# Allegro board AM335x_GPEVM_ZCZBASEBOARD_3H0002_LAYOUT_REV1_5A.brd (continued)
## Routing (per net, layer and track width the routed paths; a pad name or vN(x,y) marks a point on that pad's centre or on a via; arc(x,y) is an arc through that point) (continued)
GND_ETH: length 22.4
  TOP w0.508: C272.2 J15.SHLD1 J15.SHLD2 C271.2
GND_OSC0: length 14.5
  TOP w0.254: v1(100.29,83.02) 100.29,84.19 98.58,85.89 95.19,85.89 94.23,86.85 93.53,86.85 93.12,86.44 92.31,86.44 92.07,86.2 U2.V11 ; C4.2 102.02,81.19 101.64,81.57 v1(101.64,81.83) 101.64,82.08 C5.2
  BOTTOM w0.254: v1(100.29,83.02) 100.6,82.71 100.62,82.71 C67.2 101,82.33 101.13,82.33 v1(101.64,81.83)
GND_OSC1: length 13.8
  TOP w0.102: U2.A5 77.94,81.14 77.1,81.14
  TOP w0.121: 77.1,81.14 76.22,81.14 75.24,80.16 71.56,80.16 71.31,79.92 67.56,79.92 C2.1 C3.1
GNDA_ADC: length 44.3
  TOP w0.305: v2(81,83.4) U2.E8
  TOP w0.508: v1(49.44,75.73) v1(57.19,75.73) ; v1(58.9,84.75) 59.66,84.75 59.92,84.49 64.16,84.49 v1(64.17,84.5) 64.41,84.75 R45.1
  BOTTOM w0.127: 79.56,82.99 79.79,83.22 79.79,83.6 80.05,83.86 80.54,83.86 v2(81,83.4)
  BOTTOM w0.152: 77.15,83.1 79.03,83.1 79.13,82.99 79.56,82.99
  BOTTOM w0.508: v1(58.9,84.75) 58.89,84.73 58.89,81.93 58.88,81.93 58.88,80.73 57.19,79.03 v1(57.19,75.73) ; C63.2 v1(49.44,75.73) ; 77.15,83.1 76.04,83.1 FB10.1 74.46,82.77 74.46,82.97 74.08,83.35 73.06,83.35 72.16,84.25 71.27,84.25 71.03,84.49 R461.1 64.19,84.49 v1(64.17,84.5)
GNDA_TSC: length 61.2
  TOP w0.121: R45.2 57.12,83.73 53.95,80.56 47.98,80.56 46.69,79.27 44.4,79.27 43.61,80.07 43.61,80.09 v1(43.29,80.4) ; 49.82,57.31 J9.11
  TOP w0.508: R45.2 65.19,83.48 R51.2 C13.2 C14.2 C11.2 C12.2
  BOTTOM w0.121: 49.82,57.31 50.96,57.31 51.22,57.57 51.22,64.68 50.07,65.83 47.73,65.83 42.18,71.38 42.18,79.29 v1(43.29,80.4)
GNDUSB0: length 26
  TOP w0.635: v1(124.62,168.26) 124.91,168.55 J14.S4 126.62,166.82 126.87,166.57 126.87,166 J14.S2 ; J14.S1 134.08,166 134.82,166.74 J14.S3 136.66,168.55 v1(136.94,168.26) FB14.2
  BOTTOM w0.635: v1(124.62,168.26) v1(136.94,168.26)
GNDUSB1: length 16.7
  TOP w0.635: J18.S1 154.6,165.66 FB19.2
  BOTTOM w0.635: J18.S1 151.94,168.31 139.98,168.31 J18.S2
GNDUSBJ: length 24.9
  TOP w0.635: FB25.1 2.02,92.62 v1(1.64,93) 1.64,95.17 J40.S4 3.3,95.38 3.98,96.05 J40.S2 ; 1.52,103.67 1.64,103.79 v1(1.64,105.52) ; 1.52,103.67 3.37,103.67 3.98,103.06 J40.S1 ; 1.52,103.67 J40.S3
  BOTTOM w0.635: v1(1.64,93) v1(1.64,105.52)
V1_2D: length 3.7
  TOP w0.121: 149.28,16.82 149.26,16.8
  TOP w0.381: 149.28,16.82 U12.5 150.47,17.88 C159.1
  BOTTOM w0.762: v1(152.95,17.31) 152.8,17.58 C242.1
V1_2D_EN: length 2.8
  TOP w0.381: v1(147.61,20.74) 147.98,20.37 U12.3
  BOTTOM w0.121: v1(147.61,20.74) 147.36,20.48 147.36,19.98 147.1,19.72 R478.1
V1_8D: length 285.7
  TOP w0.279: v1(23.84,105.57) 23.77,105.64 U28.17
  TOP w0.305: U15.16 v1(21.87,135.18) ; U13.16 21.74,116.13 v1(21.86,116.24) ; U16.16 v1(21.87,128.83) ; J11.62 4.74,128.82 v1(4.36,129.2) ; v1(4.36,111.42) 4.61,111.67 J11.8 ; U14.16 v1(21.87,122.48)
  TOP w0.508: C133.1 v1(135.8,128.46) 134.33,129.93 131.49,129.93 129.37,132.05 v1(120.18,132.05) 119.72,132.05 118.19,133.59 104.87,133.59 104.2,134.26 98.05,134.26 97.94,134.15 97.44,134.15 97.3,134.01 87.44,134.01 86.85,134.6 84.67,134.6 80.67,130.59 66.59,130.59 66.21,130.97 62.52,130.97 61.38,132.12 57.23,132.12 54.23,135.11 51.65,135.11 50.94,134.41 42.58,134.41 41.44,135.55 34.96,135.55 30.39,140.12 27.6,140.12 26.96,140.75 23.91,140.75 ; 23.91,140.75 18.96,145.71 18.96,147.48 18.2,148.25 16.17,148.25 14.13,150.28 R358.2 ; 23.91,140.75 23.28,140.12 23.28,135.93 22.53,135.18 v1(21.87,135.18) ; v1(4.36,129.2) 4.36,129.83 5.52,131 16.65,131 19.47,128.18 21.62,128.18 21.87,128.43 v1(21.87,128.83) ; v1(133.01,50.52) 130.53,50.52 128.37,48.36 120.88,48.36 119.44,46.93 v1(116.42,46.93)
  LY3 w0.508: v1(23.84,105.57) 23.13,104.86 18.27,104.86 17.99,105.14 v1(17.39,105.14)
  LY4 w0.483: 132.75,87.13 J8.2 133.56,86.52
  LY4 w0.514: J3.1 136.71,124.37 ; J3.1 135.8,123.46 ; J3.1 135.8,125.28 ; J3.1 134.89,124.37
  BOTTOM w0.305: R334.2 v1(4.61,112.31) ; R329.2 v1(4.48,123.74) ; v1(4.61,118.02) R331.2 R332.2 ; R330.2 v1(4.48,121.45)
  BOTTOM w0.381: R333.2 3.59,114.59
  BOTTOM w0.508: R472.1 116.33,47.02 v1(116.42,46.93) 115.18,46.93 C261.1 ; R519.2 19.72,117.51 ; 19.72,117.51 19.72,116.62 19.97,116.37 ; 19.72,117.51 19.72,120.31 20.35,120.93 20.35,122.72 ; 19.97,116.37 C164.1 21.63,116.37 21.75,116.24 v1(21.86,116.24) ; 19.97,116.37 19.97,115.68 19.52,115.23 18.3,115.23 17.77,114.69 17.77,110.6 16.87,109.71 16.87,105.6 17.33,105.14 v1(17.39,105.14) ; 3.59,123.74 3.59,128.43 v1(4.36,129.2) ; 3.59,123.74 3.59,121.45 ; 3.59,123.74 v1(4.48,123.74) ; 4.23,112.31 4.23,111.54 v1(4.36,111.42) 3.21,111.42 C162.1 ; 4.23,112.31 v1(4.61,112.31) ; 4.23,112.31 3.59,112.31 3.59,118.02 ; 3.59,121.45 v1(4.48,121.45) ; 3.59,121.45 3.59,118.02 ; 20.35,122.72 21.63,122.72 v1(21.87,122.48) ; 20.35,122.72 19.98,123.09 19.98,128.31 20.23,128.56 20.23,129.07 ; v1(21.87,135.18) 21.63,135.42 C168.1 20.48,135.42 19.98,134.91 19.98,129.32 20.23,129.07 ; 20.23,129.07 C170.1 21.63,129.07 v1(21.87,128.83) ; 3.59,118.02 v1(4.61,118.02) ; v1(23.84,105.57) 23.66,105.75 C87.1 ; C138.1 132.63,86.65 J8.2 ; J3.1 v1(135.8,128.46)
V1_8FTDI: length 36.3
  TOP w0.254: v1(18.81,82.74) 18.81,83.93 U58.49 ; v1(11.34,82.69) 11.27,82.76 U58.64 ; U58.37 v1(19.37,76.52)
  TOP w0.305: 13.65,76.77 13.4,76.52 U58.12 8.04,76.52 v1(8.01,76.49) 7.61,76.08 7.61,75.4 6.92,74.71 v1(6.08,74.71) C330.1 ; 13.65,76.77 13.78,76.9 18.99,76.9 v1(19.37,76.52) ; 13.65,76.77 13.65,78.85 13.47,79.02 13.47,80.56 ; 13.47,80.56 v1(11.34,82.69) ; 13.47,80.56 16.62,80.56 v1(18.81,82.74)
  BOTTOM w0.254: C316.1 18.71,82.84 v1(18.81,82.74) ; v1(19.37,76.52) 20.2,76.52 C324.1 ; C321.1 v1(11.34,82.69) ; C327.1 v1(8.01,76.49)
V3_3D: length 237.9
  TOP w0.203: C191.1 27.49,56.16 v1(28.15,56.16) 28.34,56.34 28.62,56.34 28.65,56.37 28.65,56.37 29.05,56.37 29.27,56.16 U25.4
  TOP w0.254: U60.5 10.45,51.42 v1(10.83,51.04) ; U32.6 v1(66.86,33.53)
  TOP w0.381: C140.1 50.08,65.7 49.82,65.44 49.82,63.66 ; C318.2 v1(6.03,54.67) ; FB15.1 v1(23.91,47.79) ; C319.2 v1(10.83,51.04) ; v1(29.91,67.37) 27.32,67.37 26.35,66.41 19.6,66.41 19.42,66.59 17.06,66.59 v1(16.55,67.09) R593.1 ; U55.5 v1(6.75,55.6)
  TOP w0.508: C222.1 67.09,32.61 66.86,32.84 v1(66.86,33.53) ; U54.3 v1(19.79,95.6) ; R386.2 156.88,141.77 155.99,140.88 137.22,140.88 135.95,142.15 129.96,142.15 128.71,143.39 123.19,143.39 116.05,150.53 114.74,150.53 113.98,149.77 112.43,149.77 111.8,149.14 94.91,149.14 92.11,146.34 v1(75.09,146.34)
  TOP w0.635: 58.52,38.7 58.97,39.15 v1(65.95,39.15) v1(71.03,39.15) v1(73.57,39.15) ; 58.52,38.7 58.52,35.73 R544.2 58.77,35.1 59.94,33.93 C359.1 64.65,32.93 64.74,32.84 66.86,32.84 ; 58.52,38.7 v1(46.97,38.7) ; v1(64.3,45.88) 63.09,44.68 59.03,44.68 57.82,45.88 50.33,45.88 v1(48.3,47.92)
  LY4 w0.514: J6.15 70.67,125.64 ; J6.15 68.85,125.64 ; J6.15 69.76,126.55 ; J6.15 69.76,124.73 ; 48.17,136.16 J5.39 ; J5.39 48.17,137.98 ; J5.39 49.08,137.07 ; J5.39 47.26,137.07 ; 50.63,63.66 49.82,63.66 49.82,64.27
  BOTTOM w0.254: U27.6 65.59,46.03 C215.1
  BOTTOM w0.381: v1(28.15,56.16) 28.14,56.17 C191.1 ; v1(10.83,51.04) v1(12.61,51.04)
  BOTTOM w0.508: v1(64.3,45.88) 64.3,46.26 64.07,46.48 64.07,47.37 65.06,48.36 65.06,49.16 65.85,49.95 C358.1 ; J6.15 69.76,124.24 C134.1 ; C135.1 v1(48.93,135.29)
  BOTTOM w0.635: v1(46.97,38.7) v1(46.97,47.86) ; R455.2 v1(65.95,39.15) ; R454.2 v1(71.03,39.15) ; 73.57,40.42 v1(73.57,39.15) ; C215.1 v1(64.3,45.88)
  BOTTOM w0.762: v1(102.91,22.26) 102.91,25.56 105.75,28.41 105.75,40.83 106.87,41.95 106.87,41.96 107.32,42.4 107.33,42.4 107.66,42.73 107.66,45.01 107.61,45.06 R68.1
  vias: v1(113.45,24.55) v1(113.45,23.66) v1(113.45,22.77)
V3_3ETHJCK: length 8.3
  TOP w0.508: J15.2 23.79,12.61 23.15,13.25 TP51.1
V3_3FTDI: length 23.4
  TOP w0.254: v1(15.28,82.61) 15.28,83.97 U58.56 ; U58.50 18.27,82.96 v1(17.92,82.61) ; U58.31 v1(18.27,73.93) ; U58.20 v1(12.77,73.91) ; U58.42 v1(19.46,79.02)
  TOP w0.508: U61.6 v1(12.48,96.3) 12.48,97.19 C334.1 ; v1(16.8,96.71) U54.5 17.88,97.25 17.69,97.44 17.69,98.07 17.83,98.21 C311.1 ; R588.2 v1(14.64,88.84) ; U61.8 v1(9.94,96.33)
  TOP w0.635: v1(1.97,77.89) FB24.2 FB23.2
  BOTTOM w0.508: C328.1 v1(15.28,82.61) ; v1(14.39,74.84) C331.2 R585.2 ; C322.1 18.27,73.11 v1(18.27,73.93) ; C317.1 12.77,73.15 v1(12.77,73.91) ; C325.1 20.35,79.02 v1(19.46,79.02)
V5_0D: length 79.5
  TOP w0.121: U24.E2 U24.E1
  TOP w0.381: J7.2 J7.1 ; U11.11 v1(136.19,12.1)
  TOP w0.508: v1(132.63,126.78) C132.1
  TOP w0.635: 143.1,146.79 U29.2 ; 143.1,146.79 144.37,146.79 ; 143.1,146.79 136.05,146.79 ; 136.05,146.79 U22.3 ; 136.05,146.79 134.78,146.79 U22.2 ; 144.37,146.79 148.64,146.79 C270.1 ; 144.37,146.79 U29.3
  TOP w0.762: C137.1 139.23,88.05 137.71,86.52 J7.2
  TOP w1.27: v1(133.01,10.32) 133.01,5.88 133.62,5.27 142.18,5.27 v1(142.96,4.48)
  LY4 w0.483: 135.11,86.52 J7.1 135.93,87.13 ; 137.2,87.13 J7.2 138.01,86.52
  LY4 w0.514: J3.2 133.26,125.28 ; J3.2 133.26,123.46 ; J3.2 132.35,124.37
  BOTTOM w0.381: 148.12,147.1 148.37,147.1
  BOTTOM w0.508: 148.37,147.1 v1(149.52,148.25) ; v1(132.63,126.78) 133.26,126.15 J3.2
  BOTTOM w0.635: C157.1 136.19,13.11 v1(136.19,12.1) 133.01,12.1 133.01,12.1
  BOTTOM w0.762: C136.1 134.66,86.52 J7.1 ; R276.2 R275.2 v1(142.96,4.48)
  BOTTOM w1.27: v1(128.43,26.2) 128.43,22.01 132.24,18.2 v1(132.24,16.93) 133.01,16.17 v1(133.01,10.32)
V5_0D_EN: length 1.6
  TOP w0.121: U24.A4 156.79,144.78 R386.1
V5_0HDMICONN: length 5.8
  TOP w0.305: v1(143.66,9.77) J10.18
  TOP w0.381: v1(144.82,11.09) 144.41,11.49 143.5,11.49 U11.13
  BOTTOM w0.635: 144.9,11.01 v1(144.82,11.09) C158.1
  BOTTOM w0.762: 144.9,11.01 v1(143.66,9.77)
VBAT: length 301.9
  TOP w0.121: U24.A1 U24.A2
  TOP w0.203: U4.3 88.05,30.18 88.02,30.15 88.02,29.85 87.67,29.5 v1(87.67,29.48) ; v1(90.53,37.63) 90.45,37.55 U4.28 ; v1(93.33,36) 93.07,35.75 93.07,35.7 92.87,35.49 U4.23 ; 87.11,37.15 87.25,37.01 U4.36 ; 85.67,31.44 85.67,31.7 85.87,31.89 U4.47 ; v1(89.16,29.4) 89.16,29.6 89.25,29.68 U4.6 ; 85.51,34.29 U4.41 ; 93,31.49 U4.13
  TOP w0.381: R239.2 v1(126.91,79.79) ; v1(149.39,20.74) 149.28,20.63 U12.1 ; v1(85.29,34.29) 85.51,34.29 ; v1(59.73,99.99) 60.3,99.99 60.55,100.24 61.47,100.24 61.56,100.14 61.76,100.14 62.14,99.76 C8.1 ; 93,31.49 93.34,31.15 v1(93.61,31.15) ; v1(85.25,30.01) 85.25,30.02 85.25,31.03 85.67,31.44 ; v1(86.91,37.63) 86.97,37.57 86.97,37.29 87.11,37.15
  TOP w0.502: TP25.1 88.81,21.4 ; TP25.1 87.77,20.36 ; TP25.1 89.85,20.36 ; TP25.1 88.81,19.32 ; 77.23,10.2 SW1.2 ; SW1.2 78.14,11.11 ; SW1.2 79.06,10.2 ; SW1.2 78.14,9.28
  TOP w0.508: R629.2 v1(14.9,16.17) ; C8.1 63.16,99.61 63.6,100.05 U63.6 ; v1(86.91,37.63) 86.6,37.93 86.6,39.36 86.3,39.66 C238.1 ; U54.1 v1(17.88,93.13) 17.88,91.78 C312.1
  TOP w0.635: U17.2 12.08,151.55 C173.1 14.77,151.55
  TOP w0.762: C214.1 v1(107.86,158.28) ; C139.1 129.61,85.76 129.96,86.11 129.96,86.14 130.34,86.52 J8.1
  TOP w1.016: v1(149.39,20.74) 149.39,21.5 148.88,22.01 144.56,22.01 143.04,20.48 142.15,20.48 v1(142.02,20.61) ; 23.28,152.54 21.92,151.18 15.13,151.18 14.77,151.55 ; 23.28,152.54 v1(33.31,152.54) v1(33.31,151.14) ; 23.28,152.54 23.28,154.65 21.86,156.07 19.66,156.07 18.71,157.02 18.71,161.95 18.73,161.97 v1(18.73,165.31) v1(18.73,167.04)
  LY3 w0.508: v1(14.9,16.17) 15.66,16.17 16.55,17.06 23.91,17.06 25.69,18.83 44.74,18.83 45.5,19.6 47.92,19.6 50.96,22.64 v1(51.98,22.64) ; v1(31.91,101.51) 28.87,98.46 20.23,98.46 17.88,96.11 v1(17.88,93.13)
  LY3 w1.016: v1(63.54,123.23) 59.82,123.23 59.71,123.33 49.31,123.33 48.4,124.24 40.04,124.24 39.13,123.33 34.56,123.33 33.95,122.72 v1(31.91,122.72)
  LY4 w0.483: 131.48,87.13 J8.1 130.67,86.52
  LY4 w0.508: v1(59.73,99.99) 56.93,102.78 52.74,102.78 52.23,103.29 50.46,103.29
  LY4 w0.514: 123.74,61.54 J19.1 ; J19.1 122.82,62.46 ; J19.1 124.65,62.46 ; J19.1 123.74,63.37 ; 122.82,59.92 J19.2 ; J19.2 124.65,59.92 ; J19.2 123.74,60.83 ; J19.2 123.74,59 ; TP25.1 88.81,21.4 ; TP25.1 89.85,20.36 ; TP25.1 87.77,20.36 ; TP25.1 88.81,19.32 ; SW1.2 79.06,10.2 ; SW1.2 77.23,10.2 ; SW1.2 78.14,11.11 ; SW1.2 78.14,9.28 ; J16.5 108.77,159.93 ; J16.5 107.86,159.02 ; J16.5 106.95,159.93 ; J16.5 107.86,160.84
  BOTTOM w0.381: 64.14,124.68 64.14,124.15 C141.1
  BOTTOM w0.508: C160.1 v1(149.39,20.74)
  BOTTOM w0.762: R80.2 34.58,166.28 34.45,166.15 ; 21.5,166.09 R83.2 ; R82.2 25.82,165.77 ; 30.26,165.77 R81.2
  BOTTOM w1.016: v1(18.73,165.31) v1(18.73,167.04) 19.66,167.04 20.61,166.09 21.5,166.09 21.82,165.77 34.07,165.77 34.45,166.15 ; v1(85.25,30.01) 85.25,30.01 85.26,30.01 85.64,29.63 85.64,28.64 84.72,27.72 C236.1 ; 86.91,37.76 v1(86.91,37.63) C253.1 ; v1(90.53,37.63) 90.53,36.63 C250.1 ; v1(93.33,36) 94.77,36 C251.1 ; v1(63.54,123.23) 63.54,124.08 64.14,124.68 64.14,125.1 J6.19 ; v1(31.91,101.51) v1(31.91,122.72) 31.91,124.73 33.31,126.12 v1(33.31,151.14) v1(33.31,152.54) ; C252.1 88.72,30.32 89.16,29.88 v1(89.16,29.4) ; v1(87.67,29.48) 87.54,29.6 87.54,30.43 C254.1 ; C240.1 92.38,31.15 v1(93.61,31.15)
  vias: v1(83.48,20.36) v1(84.75,20.36) v1(85.76,20.36) v1(157.77,148.5) v1(158.53,148.5)
VBUS0_OTG_CAP: length 3.7
  TOP w0.635: C182.1 131.99,153.9 J36.2
VBUS1_OTG_CAP: length 6.6
  TOP w0.502: 154.53,156.67 J37.2 ; J37.2 154.53,158.75 ; J37.2 153.49,157.71
  TOP w0.635: C185.1 J37.2
VDD1_SMPS: length 25
  TOP w0.254: U32.8 v1(67.79,35.15)
  TOP w0.635: 79.39,45 v1(75.54,45) 73.36,45 73.1,44.74 v1(71.79,44.74) v1(71.79,45.38) ; R46.1 73.68,36.85 74.12,36.4 v1(74.91,36.4)
  LY3 w0.514: 123.74,48.84 J19.6 ; J19.6 123.74,50.67 ; J19.6 124.65,49.76 ; J19.6 122.82,49.76
  BOTTOM w0.121: C357.1 v1(70.06,35.47)
  BOTTOM w0.635: v1(75.54,45) 74.91,44.36 v1(74.91,36.4)
  vias: v1(80.17,45.33) v1(80.56,45.96) v1(80.94,45.33)
VDD2_SMPS: length 167.9
  TOP w0.381: v1(61.8,100.72) 61.89,100.8 C6.1 62.52,101.38 62.9,101 U63.5
  LY4 w0.508: v1(61.8,100.72) 61.35,100.27 61.35,100.06 60.56,99.26 59.87,99.26 59.86,99.27 59.14,99.27 57.19,97.32 57.19,93.77 56.68,93.26 56.68,86.6 58.27,85.01 58.27,81.38 58.97,80.68 58.97,75.85 57.49,74.37 57.49,47.15 59.52,45.12 63.11,45.12 63.24,45.25 69.76,45.25
  BOTTOM w0.254: v1(70.01,46.93) 69.51,46.93 69.4,47.03 U27.8
  BOTTOM w0.508: v1(70.52,48.42) 69.76,48.42 69.25,48.93 C354.1
  BOTTOM w1.016: v1(77.76,38.26) 77.76,36.3 75.57,34.1 75.57,24.38 81.79,18.16 86.99,18.16 87.46,17.69 93.57,17.69 94.59,18.71 107.48,18.71 107.99,19.21 112.84,19.21 118.66,25.02 118.66,34.71 121.45,37.5 121.45,44.85 122.85,46.25 122.85,46.33 J19.7
  vias: v1(70.52,47.66) v1(76.62,38.26)
VDD3_SMPS: length 35.3
  TOP w0.508: v1(91.35,45.12) 92.23,45.12 R470.1 92,45.88 v1(91.35,45.88)
  TOP w0.635: R470.1 92.5,45.38 94.29,45.38 C235.1 95.99,45.74 97.01,44.72 108.96,44.72 109.99,43.69 122.75,43.69 J19.8
VDD_CORE: length 64
  TOP w0.305: U2.J12 v2(84.2,87.4)
  TOP w0.381: U2.F7 v2(82.6,82.6) U2.G7 ; U2.F6 v2(82.6,81.8) U2.G6 ; U2.L6 v2(85.8,81.8) U2.K6 ; U2.K8 v2(85.8,83.4) U2.L8 v2(86.6,83.4) ; U2.H11 v2(83.4,86.6) ; v2(88.2,87.4) U2.N12 ; U2.N13 v2(87.4,88.2) U2.M13 ; U2.N8 v2(88.2,84.2) U2.N9 ; v2(86.6,84.2) U2.L9 ; v2(85.8,87.4) U2.K12 ; v2(82.6,85.8) U2.G10 ; v2(86.6,82.6) U2.L7 ; v2(87.4,86.6) U2.M11
  TOP w0.635: C17.1 v1(67.35,73.7)
  TOP w1.016: C232.1 65.35,71.03 ; 65.35,71.03 65.19,70.86 65.19,69.86 62.01,66.69 62.01,60.92 62.14,60.79 62.14,59.47 63.35,58.26 65.26,58.26 v1(65.89,57.63) v1(66.46,57.06) v1(66.46,56.43) ; 65.35,71.03 65.35,71.7 v1(66.46,72.81) v1(66.9,73.25) v1(67.35,73.7) ; 73.32,46.39 71.16,46.39 70.54,45.78 R32.2
  BOTTOM w0.381: v2(82.6,85.8) 82.6,85.37 C19.1 ; v2(85.8,83.4) 85.65,83.4 85.19,83.86 C24.1 ; v2(86.6,84.2) 86.14,84.66 C35.1 ; v2(85.8,87.4) 85.5,87.1 C34.1 ; v2(88.2,84.2) 88.05,84.35 C36.1
  BOTTOM w0.635: C23.1 v1(70.14,72.91) ; 66.2,77 v1(65.06,77)
  BOTTOM w1.016: v1(74.97,46.65) 74.97,48.6 72.73,50.84 71.28,50.84 70.5,51.62 67.6,51.62 66.46,52.77 v1(66.46,56.43) v1(66.46,57.06) v1(65.89,57.63)
  vias: v1(73.57,46.65) v1(74.33,46.01)
VDD_MPU: length 79.2
  TOP w0.381: U2.F10 v2(81.8,85.8) U2.F11 U2.F12 v2(81.8,87.4) U2.F13 v2(82.6,88.2) U2.G13 83.06,87.8 83.18,87.92 83.62,87.92 83.74,87.8 U2.H13 v2(84.2,88.2) U2.J13
  TOP w0.635: v1(73.95,34.81) 73.85,34.71 73.19,34.71 72.68,34.2 R46.2
  LY3 w1.016: v1(62.95,62.37) v1(62.95,63.18) 62.95,63.89 v1(62.93,63.92) 62.93,66 62.84,66.09 62.84,67.33 63.71,68.21 63.71,69.63 63.49,69.86 63.49,77.46 60.92,80.02 60.92,81.09 61.64,81.81 64.92,81.81 64.93,81.83
  LY4 w1.016: v1(73.98,33.26) v1(73.98,34.05) 73.95,34.07 v1(73.95,34.81) 73.95,36.87 75.09,38.01 75.09,42.96 76.43,44.3 76.43,46.44 73.13,49.74 68.84,49.74 62.48,56.1 62.48,61.01 62.95,61.48 v1(62.95,62.37) v1(62.95,63.18) 62.95,63.89 v1(62.93,63.92)
  BOTTOM w0.381: C41.1 81.8,86.69 v2(81.8,87.4) ; v2(81.8,85.8) 81.8,85.15 C53.1 ; v2(84.2,88.2) 84.42,87.98 C83.1
  BOTTOM w0.635: v1(71.67,81.83) 71.41,81.57 C56.1 ; 69.38,81.7 70.01,82.33 v1(70.52,82.33) ; v1(65.32,80.81) 65.44,80.94 66.19,80.94 C246.1
VDD_RTC: length 6
  TOP w0.381: v2(80.2,81.8) U2.D6
  BOTTOM w0.203: v2(80.2,81.8) 80.01,81.8 79.83,81.98 79.83,81.98 79.58,82.23 79.58,82.23 79.54,82.27 79.03,82.27
  BOTTOM w0.508: C65.1 76.58,80.81 76.89,81.13 76.91,81.13 78.05,82.27 79.03,82.27
VDDA1P8V_USB0: length 82.1
  TOP w0.381: v2(88.2,90.6) U2.N16 ; v2(89.8,90.6) U2.R16
  TOP w0.508: v1(95.54,132.6) 95.77,132.83 97.14,132.83 97.33,132.63 98.07,132.63 98.58,133.15 98.58,133.29 102.55,133.29 103.21,132.63 v1(116.62,132.63) ; C61.1 v1(115.86,136.94) 115.86,138.53 114.72,139.67 114.72,141.1 R502.2
  LY4 w0.381: v2(89.8,90.6) 89.24,91.16 88.75,91.16 88.2,90.61 v2(88.2,90.6)
  BOTTOM w0.508: v1(116.62,132.63) 116.62,136.18 v1(115.86,136.94) ; v1(95.54,132.6) 95.54,131.48 95.92,131.1 95.92,128.37 95.54,127.99 95.54,116.62 96.05,116.12 96.05,112.43 94.78,111.16 94.78,106.59 95.52,105.85 95.52,103.6 92.92,101.01 92.92,97.78 91.41,96.26 91.41,95.48 90.78,94.84 89.84,94.84 89.06,94.06 89.06,91.6 88.49,91.03 88.49,90.89 v2(88.2,90.6)
VDDA3P3V_USB0: length 76.1
  TOP w0.381: v2(88.2,89.8) U2.N15 ; v2(89.8,89.8) U2.R15
  TOP w0.508: C62.1 109.58,136.88 109.58,137.82 ; 109.58,137.82 109.58,137.89 107.58,139.89 R504.2 ; 109.58,137.82 v1(109.59,137.81) ; v1(92.87,96.56) 92.87,97.08 94.32,98.52 94.32,102.57 96.4,104.66 v1(108.88,104.66)
  LY3 w0.102: v2(89.8,89.8) 89.79,89.8 ; 91.32,91.35 91.2,91.48
  LY3 w0.127: 90.19,90.19 90.92,90.19 91.05,90.32 91.05,91.2 91.04,91.2 90.32,91.2 90.19,91.07 90.19,90.19 ; 90.19,90.19 90.18,90.18
  LY3 w0.254: 90.18,90.18 v2(89.8,89.8)
  LY3 w0.508: v1(92.87,96.56) 92.87,95.16 91.2,93.48 91.2,91.35 91.05,91.2
  BOTTOM w0.102: 89.58,89.58 89.39,89.58 89.19,89.38 88.62,89.38 88.2,89.8 v2(88.2,89.8) 88.58,90.18 89.42,90.18 v2(89.8,89.8) 89.58,89.58
  BOTTOM w0.508: v1(108.88,104.66) 108.88,137.1 v1(109.59,137.81)
VDDA_ADC: length 153.9
  TOP w0.121: 124.62,160.69 124.62,160.69 124.74,160.57 124.75,160.57
  TOP w0.508: Q5.S 125.82,160.01 R565.2 124.75,160.57 v1(124.37,160.95) ; v1(58.01,86.65) 58.07,86.59 65.32,86.59 v1(65.63,86.91) 65.63,88.34 65.64,88.34 65.64,88.5 R30.1 ; v1(53.76,78.78) 48.3,78.78 v1(47.92,78.4)
  LY3 w0.508: v1(65.63,86.91) 65.63,88.24 66.74,89.34 70.06,89.34 71.11,90.38 71.11,94.09 73.11,96.1 76.49,96.1 79.18,98.79 79.18,102.5 80.68,104 80.68,106.34 82,107.66 89.78,107.66 90.97,108.85 v1(112.25,108.85)
  BOTTOM w0.381: v1(65.63,86.91) 65.25,87.29 R462.1
  BOTTOM w0.508: v1(47.92,78.4) R501.2 ; v1(112.25,108.85) 112.25,123.91 114.03,125.69 114.03,126.99 115.56,128.51 115.56,130.21 120.79,135.44 120.79,157.36 v1(124.37,160.95) ; FB9.1 53.7,78.72 v1(53.76,78.78) 55.92,78.78 58.25,81.11 58.25,82.19 58.25,82.2 58.25,85.69 58.01,85.93 v1(58.01,86.65)
VDDH_PHY: length 2.8
  TOP w0.762: C192.1 28.23,53.12 v1(28.49,53.38)
  BOTTOM w0.762: R391.2 26.71,58.2 v1(26.45,57.95) ; R389.1 v1(28.49,53.38)
VDDL_PHY: length 14.7
  TOP w0.203: U25.47 31.38,59.06 v1(31.33,59.12)
  TOP w0.508: v1(31.33,59.12) 31.28,59.17 31.28,60.36 31.41,60.49 C197.1 31.28,61.12 30.03,61.12 C256.1 28.51,61.27 L7.1 27.98,61.8 FB16.2 ; R394.1 v1(33.31,62.9)
  BOTTOM w0.508: v1(33.31,62.9) 33.31,61.63 31.33,59.65 v1(31.33,59.12) 31.53,58.91 C196.1
VDDMPU_MON: length 4.7
  TOP w0.381: R561.1 73.95,78.4 76.87,78.4 77.48,79 U2.A2
VDDR_VREF: length 80.1
  TOP w0.381: v1(95.38,63.84) U33.E1 ; v1(91.38,57.44) U33.J8 ; v1(76.78,57.44) U34.J8 ; v2(84.2,80.2) U2.J4 ; v1(80.78,63.84) U34.E1
  TOP w0.508: v1(100.25,61.04) 102.41,61.04 102.91,60.54 v1(102.91,59.45)
  LY4 w0.508: v1(100.25,61.04) 100.25,61.82 99.05,63.03 95.85,63.03 95.38,63.49 v1(95.38,63.84)
  BOTTOM w0.254: C308.1 103.29,58.01 103.66,57.64 U62.6
  BOTTOM w0.381: 77.58,59.73 77.68,59.63 77.79,59.73 ; v2(84.2,80.2) 84.72,80.2 85,79.92 R541.2 84.82,79.26 84.34,78.78 84.34,77.99
  BOTTOM w0.508: C335.2 80.62,65.7 80.59,65.67 80.58,65.67 80.26,65.35 80.26,63.84 ; 77.58,58.24 77.79,58.44 77.79,59.73 C304.1 78.52,59.73 79.35,60.56 79.35,61.37 79.39,61.41 79.39,62.48 79.59,62.67 79.59,63.71 79.72,63.84 80.26,63.84 ; 77.58,58.24 80.3,58.24 80.99,58.94 80.99,59.28 81.44,59.73 83.43,59.73 83.98,60.29 89.65,60.29 v1(90.21,59.73) C306.1 92.26,59.73 ; 77.58,58.24 77.56,58.24 76.99,57.68 76.99,57.65 v1(76.78,57.44) ; 84.34,77.99 84.29,77.94 84.29,77.27 83.99,76.97 83.99,75.75 84.54,75.2 C303.1 C309.2 R542.2 84.54,71.87 87.92,68.49 89.96,68.49 89.97,68.48 92.6,68.48 93.54,67.54 93.54,67.46 94.83,66.17 94.83,64.39 v1(95.38,63.84) 95.24,63.69 95.14,63.69 94.6,63.15 94.6,61.39 95.13,60.86 95.13,60.2 94.67,59.73 C336.2 C307.1 92.26,59.73 ; 92.26,59.73 92.26,59.04 91.38,58.16 v1(91.38,57.44) ; 80.26,63.84 v1(80.78,63.84) ; v1(102.91,59.45) 103.29,59.07 C308.1 ; 77.58,59.73 C305.1
VDDR_VTT: length 12.9
  BOTTOM w0.381: C338.1 104.66,51.83 104.66,52.18 v1(104.79,52.31) 104.66,52.44 U62.3
  BOTTOM w0.508: C277.1 100.48,51.96 99.99,52.46 v1(99.99,53.12) ; v1(89.32,67.8) 88.81,67.3 R613.1 88.68,67.09 88.45,67.09 88.32,66.97 C377.1 ; C275.1 v1(99.98,54.03) ; R609.1 89.83,67.3 v1(90.33,67.8) ; R604.1 92.87,67.25 v1(92.32,67.8) 91.86,67.35 R607.1 ; R603.2 v1(102.02,52.74) ; v1(91.32,67.8) 90.84,67.32 R606.1 ; C276.1 v1(98.46,53.12)
  vias: v1(83.96,52.95) v1(85,52.95) v1(85.99,52.95) v1(87.06,52.92) v1(88.18,52.92) v1(89.19,52.92) v1(90.21,52.95) v1(91.27,52.97) v1(92.34,52.97) v1(93.38,52.95) v1(94.42,67.83) v1(94.4,52.95) v1(95.44,67.8) v1(96.48,67.83)
VDDS_DDR: length 93.4
  TOP w0.254: U34.G2 v1(78.38,62.24) ; U34.K1 76.38,63.47 76.14,63.71 v1(76.14,64.81)
  TOP w0.381: v1(82.38,63.84) U34.C1 ; C227.1 88.98,54.6 v1(88.98,56.64) U33.M9 ; C352.2 v1(99.73,58.08) ; v1(81.58,59.04) U34.D7 ; v1(78.38,57.44) U34.G8 ; v1(83.18,56.64) U34.B9 ; U33.A2 v1(98.58,62.24) ; U34.E2 v1(80.78,62.24) ; v1(96.98,63.84) U33.C1 ; U34.A9 v1(83.98,56.64) 83.98,55.97 84.75,55.21 C226.1 ; v1(97.78,56.64) U33.B9 ; v1(74.38,63.84) U34.M1 ; v1(75.98,56.64) U34.K9 ; U33.E2 v1(95.38,62.24) ; v1(95.38,56.64) U33.E9 ; v1(98.58,56.64) U33.A9 ; v1(92.98,57.44) U33.G8 ; v1(74.38,56.64) U34.M9 ; v1(90.58,63.84) U33.K1 ; U33.G2 v1(92.98,62.24) ; U34.A2 v1(83.98,62.24) ; v1(96.18,59.04) U33.D7 ; v1(80.78,56.64) U34.E9 ; v1(88.98,63.84) U33.M1 ; v1(90.58,56.64) U33.K9
  TOP w0.635: R513.2 116.2,40.62 115.29,40.62 v1(114.85,40.17) 114.85,39.66 v1(114.59,39.41)
  LY3 w0.508: v1(114.85,40.17) 114.85,39.66 v1(114.59,39.41)
  LY3 w0.635: v1(103.03,41.69) v1(103.03,40.93) 104.56,39.41 v1(114.59,39.41)
  BOTTOM w0.254: U62.2 105.16,52.66 105.29,52.52 105.29,52.51 v1(105.5,52.31) 105.41,52.22 105.41,51.95 105.07,51.61 C339.1
  BOTTOM w0.381: v1(76.36,54.52) 76.36,53.82 76.24,53.69 C18.1 75.84,52.74 75.73,52.85 U64.6 ; C155.1 82.86,55.89 82.86,56.32 v1(83.18,56.64) ; v1(83.98,62.24) 84.33,61.89 C208.1 ; v1(74.38,63.84) 74.38,64.63 C218.1 ; 85.51,64.05 C225.1 C224.1 C208.1 ; 88.94,64.68 88.98,64.63 v1(88.98,63.84) ; v1(80.78,56.64) 80.78,56.01 C223.1 ; C203.1 v1(72.3,56.09) ; v1(92.98,62.24) 92.98,62.92 C219.1 ; v1(67.47,69.18) 68.17,69.18 C267.1 ; R630.2 87.11,61.2 85.94,61.2 85.51,61.63 C208.1 ; C336.1 94.25,60.74 v1(94.55,60.44) ; C221.1 80.78,63 v1(80.78,62.24) ; C195.1 96.98,64.64 v1(96.98,63.84) ; R631.2 78.46,53.76 78.9,54.2 v1(78.9,54.49) 79.34,54.49 C125.1 ; v1(81.58,59.04) 81.58,58.45 C126.1 ; v1(95.38,56.64) 95.38,56.01 C189.1 ; v1(78.38,62.24) 78.38,62.92 C216.1 ; v1(75.98,56.64) 75.98,55.8 C220.1 ; C188.1 92.98,58.18 v1(92.98,57.44) ; C156.1 95.38,63 v1(95.38,62.24) ; v1(97.78,56.64) 97.47,56.32 97.47,55.89 C181.1 ; v1(82.38,63.84) 82.38,64.64 C217.1 C335.1 ; C174.1 90.58,55.8 v1(90.58,56.64)
  BOTTOM w0.508: C278.1 v1(108.62,51.8) ; v1(110.15,55.33) C340.1 R597.2 ; C279.1 v1(106.59,51.8)
  BOTTOM w0.635: v1(96.58,55.03) v1(97.47,55.03) 96.98,54.53 96.98,54.4 96.87,54.3 96.87,53.72 96.98,53.62 96.98,47.8 100.9,43.88 101.8,43.88 103.03,42.65 v1(103.03,41.69) v1(103.03,40.93)
  BOTTOM w0.762: C280.1 v1(101.88,68.76)
VDDS_OSC: length 47.9
  TOP w0.305: U2.R11 v2(89.8,86.6)
  LY4 w0.508: v1(102.97,81.06) 101.38,81.06 101,81.44 101,83.48 100.49,83.98 97.31,83.98 96.17,82.84 94.66,82.84 93.51,84 93.51,85.25 v1(93.79,85.53)
  BOTTOM w0.381: v1(93.79,85.53) 90.87,85.53 v2(89.8,86.6)
  BOTTOM w0.508: R506.1 113.54,65 110.72,65 110.5,65.21 110.5,77.58 107.02,81.06 v1(102.97,81.06) 101.26,81.06 C67.1
VDDS_PLL_CORE_LCD: length 39.4
  TOP w0.102: U2.R10 89.41,85.4
  TOP w0.381: 89.41,85.4 v2(89.8,85.01)
  LY4 w0.508: v1(99.35,81.89) 98.26,81.89 97.94,82.21 94.4,82.21 91.02,85.58 90.36,85.58 90.02,85.24 90.02,85.23 v2(89.8,85.01)
  BOTTOM w0.508: R503.1 107.51,65.67 C64.1 108.78,65.7 109.74,66.65 109.74,77.3 106.62,80.43 100.75,80.43 100.05,81.13 100.05,81.2 99.68,81.57 99.67,81.57 v1(99.35,81.89)
VDDS_PLL_DDR: length 44.3
  TOP w0.381: U2.E7 v2(81,82.6)
  LY3 w0.102: 79.93,82.98 79.54,82.59 79.92,82.21 80.62,82.21 81,82.59 v2(81,82.6) 80.99,82.6 80.61,82.98 79.93,82.98
  LY3 w0.508: 79.54,82.59 78.65,82.59 75.41,79.35 68.81,79.35 v1(68.24,78.78)
  BOTTOM w0.508: R507.2 59.95,56.23 62.11,58.4 62.11,59.45 62.12,59.45 62.12,61.78 62.11,61.78 62.11,64.85 C73.1 62.9,66.71 65.7,69.51 65.7,70.52 68.3,73.12 68.3,75.02 68.24,75.08 v1(68.24,78.78)
VDDS_PLL_MPU: length 47.7
  TOP w0.102: U2.H15 v2(83.4,89.8)
  TOP w0.508: R497.2 94.24,115.86 v1(94.24,117)
  LY3 w0.508: v1(94.27,112.69) 92.34,112.69 91.21,113.82 85.19,113.82 84.9,113.52 v1(84.26,113.52)
  LY4 w0.102: 83,90.24 83.4,89.84 v2(83.4,89.8) 83.39,89.8 82.97,89.38 82.4,89.38 82.18,89.6 82.18,90.21 ; 83,90.24 82.97,90.21 82.18,90.21 ; 83,90.24 83,91.03 82.49,91.03 82.18,90.72 82.18,90.21
  LY4 w0.508: v1(84.49,101.13) 83.86,101.13 83.06,100.33 83.06,98.93 82.6,98.47 82.09,98.47 81.78,98.16 81.78,98.12 81.71,98.05 81.71,97.53 81.78,97.46 81.78,95.01 82.46,94.33 82.46,93.1 83,92.56 83,91.03
  BOTTOM w0.508: v1(94.27,112.69) C70.1 94.27,114.34 94.24,114.37 v1(94.24,117) ; v1(84.49,101.13) 84.04,101.58 84.04,106.4 84.26,106.62 v1(84.26,113.52)
VDDS_RTC: length 37.1
  TOP w0.305: v2(80.2,82.6) U2.D7
  BOTTOM w0.508: R505.1 63.19,49.88 63.74,49.88 63.77,49.92 64.68,50.83 64.68,52.17 64.94,52.43 64.94,56.55 64.43,57.06 64.43,58.39 65.06,59.03 C66.1 65.06,61.2 64.62,61.64 64.62,67.28 66.33,69 66.33,70.01 68.94,72.62 68.94,79.61 70.07,80.74 70.07,81.05 v1(70.52,81.5)
VDDS_SRAM_CORE_BG: length 52.3
  TOP w0.381: v2(81,84.2) U2.E9
  TOP w0.508: v1(67.6,102.78) 66.97,102.78 65.83,103.91 65.83,103.96 64.86,104.94 52.59,104.94 51.35,103.69 51.35,103.67 v1(50.2,102.53)
  BOTTOM w0.102: v2(81,84.2) 80.28,84.2 79.86,84.62 78.84,84.62
  BOTTOM w0.508: 51.09,102.4 50.33,102.4 v1(50.2,102.53) 49.97,102.75 49.11,102.75 R500.2 ; v1(67.6,102.78) 67.6,102.02 67.19,101.61 67.19,99.1 67.09,99 67.09,93.7 67.44,93.35 67.44,89.97 68.92,88.5 71.26,88.5 72.05,87.71 72.05,87.16 73.51,85.7 74.53,85.7 75.86,84.37 78.59,84.37 78.84,84.62
VDDS_SRAM_MPU_BB: length 60.9
  TOP w0.381: v2(80.2,85.8) U2.D10
  TOP w0.508: v1(67.22,107.4) 66.36,106.54 58.84,106.54 57.97,107.4 v1(51.93,107.4)
  BOTTOM w0.381: v2(80.2,85.8) 79.98,86.02 79.96,86.02 79.59,86.38
  BOTTOM w0.508: v1(51.93,107.4) 51.93,98.92 C69.1 ; 79.59,86.38 77.41,86.38 76.82,86.97 73.25,86.97 72.68,87.54 72.68,87.98 71.52,89.14 69.62,89.14 68.08,90.68 68.08,93.67 67.73,94.02 67.73,98.74 67.82,98.83 67.82,101.34 68.25,101.76 68.25,104.44 68.25,104.44 68.25,106.37 v1(67.22,107.4)
  BOTTOM w0.635: C69.1 50.2,97.95 v1(50.08,98.08) 49.28,98.08 R499.2
VDDSHV1: length 385.1
  TOP w0.305: U9.12 148.75,97.7 v1(148.37,98.08) ; U9.37 148.76,117.38 v1(148.5,117.64) ; v1(147.53,117.66) 147.76,117.44 U9.39 ; U9.34 v1(150.26,117.66)
  TOP w0.381: U15.2 24.93,135.83 v1(24.7,136.05) 24.7,136.16 25.02,136.48 U15.3 ; U15.1 24.81,135.18 v1(24.65,135.01)
  TOP w0.635: v1(150.26,117.66) 150.48,117.89 150.48,118.45 C130.1 C131.1 147.53,118.45 v1(147.53,117.66) ; v1(148.37,95.29) 148.5,95.16 C128.1 148.5,93.84 148.86,93.48 152.64,93.48 153.45,94.3 v1(153.45,95.64) ; v1(148.37,98.08) 148.37,98.31 147.76,98.92 145.66,98.92 v1(145.57,98.82)
  TOP w0.762: v1(27.22,83.35) 42.35,83.35 45.45,86.45 v1(47.92,86.45) 54.09,86.45 v1(54.65,85.89) ; v1(25.12,154.66) 30.45,154.66 31.2,153.91 56.73,153.91 59.37,151.27 62.62,151.27 63.64,150.25 66.15,150.25 69.68,146.72 73.32,146.72 73.95,147.36 90.84,147.36 93.38,149.9 111.34,149.9 112.08,150.63 113.55,150.63 114.31,151.4 117.11,151.4 123.81,144.69 129.03,144.69 130.61,143.12 139.38,143.12 140.54,141.96 v1(145.64,141.96)
  LY3 w0.635: v1(119.51,72.58) 119.54,72.58 122.43,69.7 147.29,69.7 150.95,73.35 150.95,87.45 151.68,88.18 151.68,93.86 v1(153.45,95.64)
  BOTTOM w0.635: C129.1 v1(148.5,117.64) ; v1(24.7,136.05) 24.86,136.05 25.5,135.42 C167.1 25.41,135.01 v1(24.65,135.01) ; v1(148.37,95.29) 148.5,95.41 C127.1 148.5,97.95 v1(148.37,98.08) ; R493.2 v1(119.51,72.58) ; R130.2 v1(153.45,95.64)
  BOTTOM w0.762: FB1.1 FB2.1 54.65,84.55 v1(54.65,85.89) ; 27.34,137.32 R518.2 ; 27.34,137.32 27.34,139.74 25.12,141.96 v1(25.12,154.66) ; 27.34,137.32 27.34,136.18 26.58,135.42 C167.1 25.82,133.62 25.56,133.36 25.56,129.03 ; v1(148.5,117.64) 148.47,117.66 v1(147.53,117.66) ; v1(147.53,117.66) 147.53,118.99 145.91,120.61 145.91,133.26 146.34,133.69 146.34,137.96 145.64,138.66 v1(145.64,141.96) ; v1(147.53,117.66) 146.65,116.78 146.65,105.32 146.52,105.19 146.52,100.27 145.91,99.66 145.91,99.17 v1(145.57,98.82) 145.43,98.68 145.43,97.34 R131.2 145.58,96.56 146.09,96.05 ; 25.56,129.03 C169.1 ; 25.56,129.03 25.56,124.24 25.44,124.12 25.44,119.74 27.18,117.99 27.18,114.89 27.09,114.8 27.09,107.04 27.12,107 27.12,105.97 27.02,105.87 27.02,97.89 26.58,97.45 26.58,95.21 26.81,94.98 26.81,88.89 26.58,88.66 26.58,84.06 27.22,83.43 v1(27.22,83.35)
VDDSHV2: length 76.1
  TOP w0.254: U28.5 22.27,111.25 21.63,111.9 C74.1 ; C15.1 26.96,108.37 U28.21
  TOP w0.381: v1(27.85,108.37) C15.1
  TOP w0.508: C74.1 v1(20.87,112.56) ; 27.98,111.67 v1(28.74,111.67)
  TOP w0.635: v1(111.99,100.55) 106.15,100.55 v1(105.75,100.95) ; v1(105.04,120.43) 104.98,120.49 104.05,120.49 103.71,120.84 91.38,120.84 90.78,120.24 85,120.24 83.67,118.91 78,118.91 v1(77.81,119.1)
  BOTTOM w0.635: v1(77.81,119.1) 77.81,119.65 77.63,119.82 77.63,119.85 77.05,120.43 77.03,120.43 75.75,121.71 75.75,123.48 75.37,123.86 C148.1 J6.11 ; v1(105.75,100.95) 105.66,101.05 105.59,101.05 104.37,102.27 104.37,113.19 105.57,114.4 105.57,119.91 105.06,120.43 v1(105.04,120.43) ; R545.2 111.64,96.71 FB5.1 v1(111.99,100.55)
VDDSHV3: length 10
  TOP w0.635: R546.2 132.27,136.69 128.69,136.69 127.86,137.51 FB21.1 FB20.1
VDDSHV4: length 55.8
  TOP w0.254: U19.10 v1(56.87,144.06)
  TOP w0.381: U20.10 v1(71.92,148.12)
  TOP w0.508: C255.1 v1(54.1,145.03) ; J13.19 54.73,147.24 54.46,146.98 v1(54.27,146.98) 54.08,146.98 53.87,147.18 J13.4
  TOP w0.635: v1(128.12,142.28) 128.12,142.28 127.87,142.53 122.97,142.53 115.73,149.77 v1(115.35,149.77)
  BOTTOM w0.635: R373.2 R372.2 56.55,166.28 55.66,165.39 v1(55.66,164.38) ; v1(48.17,149.9) 48.55,149.52 R366.2 R368.2 R367.2 ; R494.2 134.37,130.97 133.13,130.97 131.61,132.5 130.91,132.5 FB4.1 130.4,134.85 128.12,137.13 v1(128.12,142.28) ; v1(54.27,146.98) 53.76,147.48 C180.1 ; v1(46.14,164.38) 46.14,165.9 46.52,166.28 R370.2 R371.2 ; R365.2 46.39,149.52 v1(46.01,149.9) ; R369.2 v1(43.09,148.88)
VDDSHV5: length 227.4
  LY3 w0.762: v1(24.55,52.62) 24.55,50.71 25.44,49.82 27.72,49.82 28.1,50.2 39.66,50.2 40.15,49.71 50.2,49.71 51.49,48.42 56.81,48.42 58.2,49.82 112.14,49.82 112.97,50.65 112.97,50.74 114.53,52.3 v1(114.53,58.39) ; v1(103.06,139.74) 109.77,139.74 111.42,138.09 v1(114.59,138.09) ; v1(130.4,128.46) 127.74,128.46 127,129.2 126.37,129.2 126.12,129.45 114.72,129.45 v1(114.59,129.32)
  LY4 w0.762: v1(24.17,59.85) 24.17,59.09 24.55,58.71 v1(24.55,52.62) ; v1(114.53,58.39) 114.59,58.46 116.75,58.46 117.89,59.6 117.89,63.92 117.75,64.06 117.75,71.04 115.61,73.19 115.61,93.13 114.59,94.14 v1(114.59,129.32) v1(114.59,138.09)
  BOTTOM w0.381: R388.2 v1(24.55,52.62)
  BOTTOM w0.508: R409.2 24.55,59.47 v1(24.17,59.85)
  BOTTOM w0.635: FB6.1 v1(114.53,58.39)
  BOTTOM w0.762: FB3.1 v1(130.4,128.46) ; R495.2 v1(103.06,139.74)
VDDSHV6: length 207.8
  TOP w0.381: v1(24.8,117.64) 25.02,117.43 U13.3 ; v1(77.7,102.45) 77.7,100.94 77.89,100.76 77.89,100.23 77.7,100.05 77.7,99.28 v1(77.99,99) ; R568.2 v1(130.87,33.84) ; v1(67.6,103.54) 67.73,103.42 67.77,103.42 68.17,103.02 68.17,102.54 67.86,102.23 R634.2 ; R306.2 v1(130.82,31.43) ; R378.2 63.29,145.06 U21.1 ; U14.1 27.23,122.48 v1(27.47,122.72) 27.06,123.13 U14.2 ; U16.2 24.96,129.48 v1(24.68,129.2) 25.05,128.83 U16.1 ; U11.24 144.67,18.6 v1(144.94,18.33) ; FB12.2 165.58,18.33 166.12,18.33 v1(166.14,18.31) ; U7.8 v1(138.4,69) ; R570.2 v1(130.82,30.29) ; R567.2 v1(130.87,32.55) ; D8.2 v1(159.68,17.44) ; U13.1 25.19,116.13 24.86,115.79 v1(24.85,115.79)
  TOP w0.635: R378.2 v1(63.16,145.96) ; J2.5 v1(22.01,94.27) ; R589.2 v1(8.55,49.41) ; v1(21.37,64.93) 24.68,64.93 25.06,64.55 C213.1 25.05,63.79 U26.5 ; R412.1 146.91,155.36 146.09,156.18 v1(146.09,157.2) ; v1(52.93,81.25) 52.23,81.25 52.23,81.25 40.29,81.25 39.92,80.87 v1(25.18,80.87) ; R382.1 v1(138.98,151.99) 138.95,151.99 138.71,152.24 138.71,154.64 139.42,155.36 144.31,155.36 145.33,156.37 v1(145.33,157.14)
  LY3 w0.381: 70.9,99.1 71.54,99.73 77.51,99.73 77.99,99.25 v1(77.99,99) ; 70.9,99.1 v1(70.65,98.84) ; 70.9,99.1 70.52,99.1 69.89,99.73 69.89,101.26 69.25,101.89 69.25,102.46 68.17,103.54 v1(67.6,103.54) 67.03,103.54 66.46,102.97 66.46,98.46 65.82,97.83 55.16,97.83 v1(54.9,98.08)
  BOTTOM w0.381: v1(77.7,102.45) 77.7,102.35 77.76,102.3 R554.2 R555.2 ; v1(70.65,98.84) 70.68,98.81 70.68,98.5 71.03,98.15 R553.2 R552.2 ; C149.1 v1(144.94,18.33) ; v1(138.4,69) 138.59,69 C116.1 v1(139.74,68.87) R72.2 ; R548.2 R547.2 78.52,98.46 v1(77.99,99) ; R559.2 v1(10.83,49.31)
  BOTTOM w0.508: v1(166.14,18.31) 164.88,18.31 C243.1 ; R98.2 R99.2 v1(165.82,61.51) ; v1(165.82,78.96) 165.76,79.03 R109.2 R108.2 ; R104.2 R105.2 v1(165.82,89.19) ; R100.2 R101.2 v1(165.82,56.43) ; v1(165.82,73.9) 165.77,73.95 R111.2 R110.2 ; R106.2 R107.2 v1(165.9,84.11) ; v1(165.82,66.59) R97.2 R96.2 ; R102.2 R103.2 v1(165.82,51.35)
  BOTTOM w0.635: C115.1 v1(22.01,94.27) ; v1(27.49,88.3) 28.22,89.02 29.21,89.02 R70.2 ; 25.18,89.19 R71.2 ; 25.18,89.19 R6.2 v1(25.18,80.87) 25.18,69.38 21.37,65.57 v1(21.37,64.93) ; 25.18,89.19 25.74,89.19 v1(25.87,89.32) ; v1(54.9,98.08) 54.43,97.61 54.43,95.45 53.25,94.27 FB7.1 FB8.1 54.58,90.65 54.58,88.14 54.11,87.67 53.72,87.67 R496.2 52.93,86.88 v1(52.93,81.25) ; v1(27.47,122.72) 27.3,122.55 C165.1 ; C163.1 25.02,117.42 v1(24.8,117.64)
AM335X_AIN0: length 68.1
  TOP w0.102: 77.1,82.59 78.65,82.59 79,82.24 U2.B6
  TOP w0.121: 77.1,82.59 77.07,82.62 73.1,82.62 72.62,83.1 70.4,83.1 69.76,82.46 v1(68.87,82.46) 68.64,82.23 65.94,82.23 65.62,81.9 64.67,81.9 64.57,82.01 60.47,82.01 60.25,82.23 57.11,82.23 54.62,79.74 48.21,79.74 46.74,78.27 41.76,78.27 41.39,77.9 41.32,77.9 v1(41.01,77.58)
  BOTTOM w0.095: 47.79,56.68 49.19,56.68 49.82,56.04
  BOTTOM w0.121: v1(41.01,77.58) 41.01,71.31 47.1,65.21 47.1,57.19 47.61,56.68 47.79,56.68 ; R461.2 v1(68.87,82.46)
AM335X_AIN1: length 77.8
  TOP w0.102: v2(79.4,83.4) U2.C7
  TOP w0.121: v1(64.93,85.69) 57.51,85.69 55.36,87.84 44.72,87.84 43.42,86.55 v1(43.42,85.53)
  BOTTOM w0.095: 49.82,54.77 49.19,55.41 47.79,55.41
  BOTTOM w0.102: 77.1,83.54 77.73,83.54 77.79,83.48 78.84,83.48 78.92,83.4 v2(79.4,83.4)
  BOTTOM w0.121: R462.2 64.43,86.2 v1(64.93,85.69) 65.31,85.31 65.75,85.31 65.82,85.38 71.16,85.38 71.54,85 74.21,85 75.67,83.54 77.1,83.54 ; 47.79,55.41 47.48,55.41 46.19,56.7 46.19,65.16 40.25,71.1 40.25,77.84 40.75,78.34 40.75,80.43 43.11,82.78 43.11,85.22 v1(43.42,85.53)
AM335X_AIN2: length 74.8
  TOP w0.102: U2.B7 79,83 78.59,83.41 77.1,83.41
  TOP w0.121: v1(39.71,79.62) 40.19,79.62 40.78,79.02 46.8,79.02 48.07,80.3 54.2,80.3 56.62,82.72 60.65,82.72 60.87,82.51 64.77,82.51 64.88,82.4 65.38,82.4 65.7,82.72 65.73,82.72 67.93,82.72 69.13,83.92 69.95,83.92 70.4,84.37 70.4,84.75 70.52,84.87 74.21,84.87 75.19,83.89 76.08,83.89 76.55,83.41 77.1,83.41
  BOTTOM w0.095: 49.82,53.5 49.18,54.14 47.91,54.14
  BOTTOM w0.121: 47.91,54.14 47,54.14 45.38,55.76 45.38,64.86 39.71,70.52 v1(39.71,79.62)
AM335X_AIN3: length 73.2
  TOP w0.102: 77.1,83 U2.A7
  TOP w0.121: v1(39.27,78.68) 46.8,78.68 48.11,79.98 54.52,79.98 56.87,82.33 57.01,82.47 60.53,82.47 60.74,82.26 64.67,82.26 64.78,82.15 65.51,82.15 65.84,82.48 66.04,82.48 66.04,82.47 68.03,82.47 68.17,82.62 69.16,83.6 71.23,83.6 71.49,83.35 72.72,83.35 73.2,82.87 76.65,82.87 76.78,83 77.1,83
  BOTTOM w0.095: 49.82,52.23 49.19,52.87 47.79,52.87
  BOTTOM w0.121: 47.79,52.87 44.79,55.87 44.79,65.01 39.27,70.53 v1(39.27,78.68)
AM335X_AIN4: length 71.9
  TOP w0.102: U2.C8 79.42,84.18 v2(79.38,84.18)
  TOP w0.121: v1(43.62,83.2) 43.94,83.51 43.94,83.58 46.05,85.7 52.94,85.7 53.43,85.2 55.03,85.2 55.84,86.02 56.68,86.02 57.44,85.25 65.18,85.25 65.57,85.64 v1(65.57,85.76)
  BOTTOM w0.121: v1(43.62,83.2) 43.62,82.51 41.19,80.07 41.19,78.42 40.5,77.74 40.5,71.36 46.54,65.32 46.54,57.11 47.61,56.04 J9.13 ; v2(79.38,84.18) 78.99,84.18 78.6,83.79 75.79,83.79 74.33,85.25 71.67,85.25 71.29,85.63 66.27,85.63 66.14,85.76 v1(65.57,85.76)
AM335X_AIN5: length 77.7
  TOP w0.102: 77.1,84.13 78.38,84.13 78.71,83.8 U2.B8
  TOP w0.121: v1(42.84,88.53) 43.28,88.53 43.47,88.34 58.55,88.34 59.22,87.67 64.21,87.67 v1(64.68,88.13) ; v1(72.43,85.76) 73.44,85.76 73.81,85.39 74.41,85.39 75.42,84.38 76.29,84.38 76.54,84.13 77.1,84.13
  BOTTOM w0.121: v1(42.84,88.53) 42.84,83.04 40.4,80.61 40.4,78.45 40.02,78.07 40.02,77.95 40,77.94 40,70.79 45.86,64.93 45.86,56.25 47.33,54.77 J9.15 ; v1(64.68,88.13) 65.08,87.74 67.26,87.74 67.37,87.62 67.39,87.62 69.13,85.89 71.86,85.89 71.99,85.76 v1(72.43,85.76)
AM335X_AIN6: length 60.1
  TOP w0.095: 49.19,54.14 50.58,54.14 50.71,54.01
  TOP w0.102: 77.1,83.8 U2.A8
  TOP w0.121: 77.1,83.8 76.52,83.8 76.18,84.13 75.31,84.13 74.33,85.12 70.39,85.12 70.14,84.87 70.14,84.49 69.82,84.17 68.42,84.17 v1(68.11,83.86) ; v1(58.38,51.45) 52.39,51.45 51.73,52.11 51.73,53 50.71,54.01 ; 49.19,54.14 J9.17
  BOTTOM w0.121: v1(68.11,83.86) 67.61,83.36 67.61,75.08 67.86,74.84 67.86,74.46 67.6,74.2 67.03,74.2 65.96,73.12 65.96,72.42 65.19,71.65 65.19,69.89 61.67,66.37 61.67,61.6 61.68,61.6 61.68,59.64 61.67,59.63 61.67,59.13 58.38,55.84 v1(58.38,51.45)
AM335X_AIN7: length 210.2
  TOP w0.102: v2(79.4,85) U2.C9
  TOP w0.121: v1(83.46,151.26) 95.25,151.26 95.72,150.79 109.79,150.79 111.72,152.72 116.93,152.72 v1(118.2,153.99) ; R571.2 v1(129.45,160.13) 129.48,160.13 R23.1 ; v1(75.81,85.32) 75.81,86.32 75.48,86.65 74.65,86.65 74.52,86.78 72.05,86.78 71.68,86.41 71.68,86.41 71.67,86.4 68.49,86.4 67.85,87.04 67.85,89.4 67.56,89.7 67.14,89.7 67.01,89.57 66.67,89.57 66.54,89.7 66.12,89.7 65.87,89.44 65.86,89.44 65.63,89.21 65.46,89.21 65.19,88.94 65.19,88.31 65.19,88.3 65.19,88.02 64.2,87.03 59.03,87.03 57.97,88.09 44.27,88.09 42.38,86.2 v1(42.38,85.76)
  LY3 w0.133: v1(118.2,153.99) 123.3,153.99 v1(129.45,160.13)
  LY4 w0.102: v2(79.4,85) 77.1,87.3 77.1,87.67
  LY4 w0.133: 77.1,87.67 74.51,90.26 74.51,91.86 73.16,93.2 73.16,100.65 72.74,101.07 72.74,101.44 73,101.7 73,103.22 73.16,103.39 73.16,113.55 80.89,121.27 80.89,134.33 82.49,135.93 82.49,145.35 82.32,145.52 82.32,150.11 v1(83.46,151.26)
  BOTTOM w0.102: 77.84,84.95 77.84,84.96 78.61,84.96 78.67,85.03 79.01,85.03 79.03,85 v2(79.4,85)
  BOTTOM w0.121: v1(75.81,85.32) 76.17,84.95 77.84,84.95 ; J9.19 47.7,52.23 44.36,55.58 44.36,64.88 38.83,70.41 38.83,79.52 42.38,83.07 v1(42.38,85.76)
AM335X_ECAP0_IN_PWM0_OUT: length 46.3
  TOP w0.121: R255.2 73.81,132.77 75.53,132.77 v1(75.92,133.16) ; v1(79.89,97.01) 79.89,96.91 80.49,96.31 80.49,95.04 80.24,94.79 80.24,92.24 U2.C18
  BOTTOM w0.121: v1(75.92,133.16) 75.73,132.96 75.73,128.99 75.81,128.91 75.81,124.14 76.42,123.53 76.42,122 78.39,120.03 78.39,107.51 79.02,106.89 79.02,106.42 79.02,105.71 79.08,105.64 79.08,105.28 79.08,103.62 79.74,102.96 79.74,97.28 79.89,97.14 v1(79.89,97.01)
AM335X_EXT_WAKEUP: length 213.3
  TOP w0.102: U2.C5 79.4,81 78.93,81 78.53,80.6 78.53,80.46 78.34,80.27 77.89,80.27 77.6,80.56 77.1,80.56
  TOP w0.121: v1(65.94,147.1) 67.08,145.96 74.36,145.96 v1(75.63,144.69) ; R405.2 34.17,62.42 34.17,62.89 34.53,63.24 34.67,63.24 35.16,63.73 36.01,63.73 41.1,68.82 61.84,68.82 v1(62.29,68.36) ; 77.1,80.56 76.36,80.56 75.48,79.67 71.79,79.67 71.4,79.28 71.05,79.28 70.68,78.91 68.9,78.91 68.68,78.68 68.68,78.59 68.54,78.46 68.54,75.48 67.75,74.69 v1(67.17,74.69)
  LY4 w0.133: v1(78.78,29.5) 78.78,40.04 78.02,40.8 78.02,47.5 75.18,50.33 74.21,50.33 73.7,50.84 68.74,50.84 64.11,55.46 64.11,64.61 62.29,66.43 v1(62.29,68.36)
  BOTTOM w0.121: R207.2 76.11,144.21 v1(75.63,144.69) ; v1(65.94,147.1) 63.66,147.1 61.76,145.2 61.76,143.04 59.47,140.75 57.7,140.75 57.31,140.37 57.31,135.55 57.95,134.91 57.95,130.09 58.39,129.64 58.39,122.02 59.85,120.56 59.85,116.62 64.68,111.8 64.68,105.04 65.54,104.18 65.54,103.69 64.96,103.11 64.96,102.85 64.19,102.07 64.19,101.71 64.55,101.35 64.55,98.59 64.05,98.08 63.41,98.08 63.09,97.76 63.09,92.68 63.03,92.62 63.03,88.05 63.72,87.35 63.72,84.33 64.43,83.63 64.43,82.46 64.81,82.08 64.81,80.43 67.17,78.07 v1(67.17,74.69) 65.7,73.21 65.7,72.82 63.38,70.51 63.38,69.46 v1(62.29,68.36) ; v1(78.78,29.5) 78.52,29.76 78.52,30.26 79,30.74 80.74,30.74 83.57,33.57 R67.2
AM335X_EXTINTN: length 131.8
  TOP w0.102: 79.72,92.9 79.72,92.65 79,91.93 U2.B18
  TOP w0.121: v1(6.9,49.19) 8.04,50.33 8.04,50.41 8.34,50.71 8.42,50.71 9.14,51.43 9.14,51.9 9.22,51.97 9.22,52.34 9.14,52.41 9.14,55.28 9.12,55.3 9.12,55.67 9.14,55.69 v1(9.14,62.1) ; v1(34.71,62.8) 34.81,62.8 R479.2 ; 79.72,92.9 79.72,93.99 79.07,94.64 77.57,94.64 76.63,95.58 73.59,95.58 73.06,95.05 72.45,95.05 72.04,95.05 71.34,95.75 70.94,95.75 69.58,97.1 66.27,97.1 65.41,97.1 64.81,96.5 61.96,96.5 61.86,96.4 R324.2 61.35,95.9 61.25,95.8 59.93,95.8 59.65,95.52 57.73,95.52 55.81,93.6 48.01,93.6 47.09,92.69 39.54,92.69 38.52,93.71 34.92,93.71 34.73,93.52 v1(34.73,93.08)
  LY3 w0.133: v1(34.71,62.8) 34.01,62.1 v1(9.14,62.1)
  BOTTOM w0.121: v1(34.71,62.8) 33.72,63.79 32.22,63.79 28.78,67.23 28.78,81.78 35.3,88.3 35.3,92.51 v1(34.73,93.08) ; 6.9,47.28 v1(6.9,49.19)
AM335X_GMII1_COL: length 16.5
  TOP w0.102: v2(83.4,90.6) U2.H16
  TOP w0.121: R320.2 82.13,102.04 82.13,102.1 v1(82.46,102.42)
  LY4 w0.102: v2(83.4,90.6) 83.61,90.81 83.61,92.9
  LY4 w0.121: v1(82.46,102.42) 83.12,101.76 83.6,101.76
  LY4 w0.133: 83.6,101.76 84.49,101.76 84.94,101.32 84.94,101.32 84.94,101.31 84.94,100.71 84.59,100.37 84.03,100.37 83.69,100.02 83.69,98.05 83.27,97.62 83.27,93.98 83.61,93.64 83.61,92.9
AM335X_GMII1_CRS: length 77
  TOP w0.102: 83.54,92.9 83.47,92.83 83.47,91.36 83.8,91.03 U2.H17
  TOP w0.121: 83.54,92.9 83.54,94.61 83.46,94.7 83.46,96.18 82.91,96.72 82.91,98.34 82.38,98.86 v1(82.38,99.55) ; v1(84.09,131.18) 83.58,131.18 81.73,129.33 76.86,129.33 76.8,129.26 76.44,129.26 76.37,129.33 66.67,129.33 66.01,129.33 65.65,129.69 60.82,129.69 60.47,129.34 55.7,129.34 54.65,130.38 54.65,131.58 53.56,132.67 53.56,132.78 53.25,133.09 R316.2
  BOTTOM w0.121: v1(84.09,131.18) 83.8,130.89 83.8,121.9 82.26,120.36 82.26,119.85 81,118.59 81,106.77 81.71,106.07 81.71,101.2 81.98,100.93 81.98,99.96 v1(82.38,99.55)
AM335X_GMII1_MDIO_CLK: length 10.8
  TOP w0.102: U2.M18 v2(87,92.56)
  TOP w0.121: R433.2 90.59,96.94 90.59,95.73 v1(90.4,95.54)
  LY4 w0.102: 86.66,92.9 v2(87,92.56)
  LY4 w0.121: v1(90.4,95.54) 90.07,95.86 ; 86.66,93.61 86.66,92.9
  LY4 w0.133: 90.07,95.86 89.23,96.71 87.82,96.71 87.18,96.07 87.18,94.86 86.66,94.33 86.66,93.61
AM335X_GMII1_MDIO_DATA: length 13.8
  TOP w0.102: 87.35,92.9 87.38,92.87 87.38,91.38 U2.M17
  TOP w0.121: R434.2 93.51,99.86 v1(93.64,99.99) ; 87.35,92.9 87.35,93.64 v1(87.16,93.83)
  LY3 w0.133: v1(93.64,99.99) 92.87,99.22 91.99,99.22 91.03,98.27 90.53,98.27 89.31,97.05 89.31,95.48 87.66,93.83 v1(87.16,93.83)
AM335X_GMII1_REFCLK: length 54.3
  TOP w0.102: U2.H18 83.8,92.89 83.79,92.9
  TOP w0.121: 83.79,92.9 83.79,93.25 83.8,93.26 83.8,94.73 83.7,94.83 83.7,96.28 83.16,96.83 83.16,100.09 83.6,100.54 83.6,104.05 83.73,104.18 83.73,107.74 82.59,108.88 v1(82.21,108.88) R432.2 ; v1(93.94,131.3) 93.81,131.43 89.9,131.43 88.24,129.77 v1(85.71,129.77)
  BOTTOM w0.121: v1(85.71,129.77) 86.2,129.28 86.2,124.55 85.23,123.58 85.23,122.11 83.83,120.71 83.83,118.8 83.08,118.06 83.08,115.48 81.76,114.16 81.76,109.32 v1(82.21,108.88) ; v1(93.94,131.3) 93.39,131.86 93.39,133.39 R410.1
AM335X_GMII1_RXCLK: length 142.9
  TOP w0.102: 86.2,92.9 U2.L18
  TOP w0.121: R423.2 42.05,58.09 v1(42.05,58.94) ; v1(85.86,103.67) 85.86,103.18 86.48,102.56 86.48,100.59 86.85,100.21 86.85,97.22 85.76,96.13 85.76,94.73 85.76,94.47 86.2,94.04 86.2,92.9 ; v1(86.27,115.56) 85.6,115.56 85.49,115.45 83.27,115.45 82.74,114.91 60.23,114.91 59.73,114.42 57.24,114.42 56.96,114.69 52.75,114.69 52.52,114.92 52.26,114.92 52.04,114.69 v1(50.1,114.69)
  BOTTOM w0.121: v1(50.1,114.69) 50.1,114.11 48.62,112.63 47.79,112.63 46.96,111.8 46.79,111.8 46.13,112.46 45.96,112.46 45.79,112.29 45.79,112.11 46.45,111.46 46.45,111.29 46.27,111.12 46.1,111.12 45.45,111.77 45.28,111.77 45.11,111.6 45.11,111.43 45.76,110.77 45.76,110.6 45.59,110.43 45.42,110.43 44.76,111.09 44.59,111.09 44.42,110.92 44.42,110.75 45.08,110.09 45.08,109.92 43.04,107.88 43.04,99.51 41.46,97.93 41.46,95.34 40.77,94.65 40.77,85.86 40.77,84.82 40.48,84.52 40.48,83.32 37.31,80.15 37.31,69.65 37.34,69.65 42.3,64.69 42.3,64.49 42.31,64.48 42.31,64.19 42.46,64.05 42.46,59.35 v1(42.05,58.94) ; v1(86.27,115.56) 85.96,115.87 85.96,116.6 86.08,116.72 86.32,116.72 86.45,116.85 86.45,119.93 86.32,120.05 85.77,120.05 85.64,119.93 85.64,115.42 85.86,115.2 v1(85.86,103.67)
AM335X_GMII1_RXD0: length 143.3
  TOP w0.102: v2(87.4,90.6) U2.M16
  TOP w0.121: v1(91.41,112.49) 90.63,113.27 89.67,113.27 88.91,114.03 88.8,114.03 88.68,114.15 88.68,115.51 88.55,115.63 88.32,115.63 88.2,115.51 88.2,114.15 88.07,114.03 87.83,114.03 87.71,114.15 87.71,115.05 87.59,115.18 87.35,115.18 87.23,115.05 87.23,114.15 87.11,114.03 83.83,114.03 83.63,114.24 61.28,114.24 60.79,113.75 56.96,113.75 56.71,114 50.7,114 50.49,113.79 49.4,113.79 49.14,114.05 v1(49.14,114.49) ; R424.2 v1(41.49,56.15)
  BOTTOM w0.102: v2(87.4,90.6) 87.4,91.26 87.87,91.73 87.87,92.9
  BOTTOM w0.121: v1(91.41,112.49) 91.41,109.2 92.49,108.11 92.49,102.88 91.27,101.66 91.27,100.29 90.84,99.86 90.84,97.34 89.75,96.25 89.75,96.22 87.87,94.35 87.87,92.9 ; v1(49.14,114.49) 49.14,114.49 48.2,113.55 43.98,113.55 42.7,112.28 42.7,110.18 41.88,109.35 41.88,100.97 41.88,99.91 39.94,97.97 39.69,97.71 39.67,97.7 39.67,85.4 39.09,84.81 39.09,84.09 39.09,83.49 36.21,80.61 36.21,69 40.92,64.28 40.92,59.76 40.65,59.49 40.65,57.1 41.18,56.57 41.18,56.46 v1(41.49,56.15)
AM335X_GMII1_RXD1: length 143.5
  TOP w0.102: v2(86.6,89.8) U2.L15
  TOP w0.121: v1(48.6,110.66) 50.33,110.66 50.79,111.12 65,111.12 65.2,111.32 79.65,111.32 80.06,110.91 86.9,110.91 87.08,111.1 87.87,111.1 87.94,111.16 v1(88,111.16) ; R425.2 42.56,54.27 42.81,54.51 v1(42.81,54.57)
  BOTTOM w0.102: 85.94,92.9 85.94,92.09 85.33,91.48 85.33,90.49 85.64,90.18 86.3,90.18 86.6,89.88 v2(86.6,89.8)
  BOTTOM w0.121: v1(88,111.16) 88,110.68 88.18,110.5 88.18,109.71 88.3,109.59 88.56,109.59 88.68,109.46 88.68,107.1 87.9,106.31 87.9,99.5 87.25,98.85 87.25,95.93 87.17,95.85 87.17,94.92 86.33,94.07 86.33,93.95 85.94,93.56 85.94,92.9 ; v1(48.6,110.66) 48.91,110.98 48.91,111.04 48.93,111.06 48.93,111.42 48.47,111.87 47.98,111.87 47.13,111.02 47.13,110.85 47.9,110.07 47.9,109.9 47.73,109.73 47.56,109.73 46.79,110.5 46.61,110.5 46.44,110.33 46.44,110.16 47.22,109.39 47.22,109.22 47.05,109.05 46.88,109.05 46.1,109.82 45.93,109.82 45.76,109.65 45.76,109.48 46.53,108.71 46.53,108.54 46.36,108.37 46.19,108.37 45.42,109.14 45.25,109.14 45.08,108.97 45.08,108.8 45.85,108.02 45.85,107.85 45.68,107.68 45.51,107.68 44.74,108.46 44.57,108.46 44.4,108.29 44.4,108.12 45.17,107.34 45.17,107.17 45,107 44.83,107 44.05,107.77 43.88,107.77 43.71,107.6 43.71,99.23 43.62,99.14 42.4,97.93 42.4,95.23 41.45,94.27 41.45,83.34 37.98,79.87 37.98,70.06 43.42,64.62 43.42,55.79 42.81,55.18 v1(42.81,54.57)
AM335X_GMII1_RXD2: length 143.2
  TOP w0.102: v2(86.6,90.6) U2.L16
  TOP w0.121: v1(49.39,110.22) 50.49,110.22 50.96,110.7 65.18,110.7 65.38,110.9 79.47,110.9 79.72,110.65 79.92,110.44 92.28,110.44 v1(93.38,111.54) ; v1(42.81,53) R427.2
  BOTTOM w0.102: 88.35,92.9 88.35,91.65 87.79,91.1 87.79,90.77 87.79,90.33 87.64,90.18 87.02,90.18 v2(86.6,90.6)
  BOTTOM w0.121: v1(42.81,53) 43.88,55.05 43.88,63.26 43.88,64.76 38.4,70.24 38.4,79.7 41.87,83.16 41.87,83.52 41.87,94.02 43.04,95.18 43.04,97.96 43.8,98.72 44.13,99.06 44.13,105.09 47.16,108.11 50.59,108.11 50.72,108.24 50.72,112 50.59,112.13 49.52,112.13 49.39,112 v1(49.39,110.22) ; 88.35,92.9 88.35,94.23 90.17,96.04 90.18,96.04 92.16,98.03 92.16,101.15 v1(92.9,101.89) 93.51,102.5 93.51,111.42 v1(93.38,111.54)
AM335X_GMII1_RXD3: length 142.8
  TOP w0.102: 86.63,92.9 86.63,92.71 86.59,92.67 86.59,91.41 86.2,91.03 U2.L17
  TOP w0.121: v1(41.52,52.34) R428.2 ; 86.63,92.9 86.63,93.86 86.63,94.21 86.45,94.39 86.45,94.58 86.19,94.84 86.19,94.91 86.19,95.89 v1(86.81,96.51) ; v1(88.15,116.62) 86.8,116.62 86.78,116.63 81.73,116.63 81.11,116.01 65.19,116.01 64.27,116.93 44.7,116.93 v1(43.45,115.68)
  BOTTOM w0.121: v1(88.15,116.62) 88.15,115.78 87.86,115.49 87.86,112.48 87.45,112.08 87.45,110.24 87.69,110 87.69,107.7 87.45,107.46 87.45,99.7 86.81,99.05 v1(86.81,96.51) ; v1(43.45,115.68) 43.45,114.16 42.28,112.99 42.28,110.35 41.46,109.53 41.46,100.8 41.46,100.09 39.77,98.4 39.38,98.01 39.25,97.88 39.25,85.58 38.66,84.99 38.66,83.92 38.66,83.66 35.78,80.78 35.78,68.79 40.5,64.07 40.5,59.93 40.23,59.66 40.23,53.62 v1(41.52,52.34)
